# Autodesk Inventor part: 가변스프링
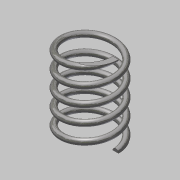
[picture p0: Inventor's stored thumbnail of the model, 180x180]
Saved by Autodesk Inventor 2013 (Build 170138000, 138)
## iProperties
Created: 2017-12
Part Number: 가변스프링
Material: 스테인리스강
Document SubType Name: Modeling
Designer: Administrator
Mass: 7.05545 g
Surface Area: 17.742 cm^2
Volume: 0.873199 cm^3
Density: 8.08 g/cm^3
Author: Administrator
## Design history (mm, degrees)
sketch "스케치1"
  geometry: L1 (0, 0)-(9, 0); L2 (9, 0)-(9, 28.5); L3 (9, 28.5)-(0, 28.5); L4 (0, 28.5)-(0, 0); C1 r 1 at (9, 0)
  constraints: 8 end point, 2 parallel, 1 centre point, 1 coincident, 1 horizontal, 1 perpendicular
  dimensions: "d0" = 18 diameter of L2 L4; "d2" = 28.5 distance of L1.end L2.end (derived); "d3" = 2 diameter of C1
feature "코일1" sketch "스케치1" pitch "d4" = 10; turns "d6" = 5; dims "d5" = 28.5 (= d2), "d7" = 0, angle "d8" = 90 deg, angle "d9" = 90 deg, "d10" = 0, "d11" = 0
node "작업 평면1"
sketch "스케치2"
  geometry: L1 (1, 0)-(-1, 0) reference; 1 further point
  constraints: 1 horizontal alignment
extrude "돌출1" cut sketch "스케치2" distance "d12" = 10; taper "d13" = 0 deg
node "작업 평면2"
sketch "스케치3"
  geometry: L1 (-1, 0)-(1, 0) reference; 1 further point
  constraints: 1 horizontal alignment
extrude "돌출2" cut sketch "스케치3" distance "d14" = 10; taper "d15" = 0 deg
node "솔리드1"
node "절단 모서리 투영1"
node "절단 모서리 투영2"
